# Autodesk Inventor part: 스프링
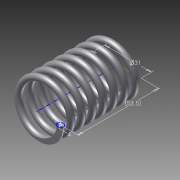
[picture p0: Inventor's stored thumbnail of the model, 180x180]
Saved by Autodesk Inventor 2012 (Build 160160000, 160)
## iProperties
Created: 2014-12
Part Number: 스프링
Material: Default
Document SubType Name: Modeling
Designer: Owner
Mass: 9.02095 g
Surface Area: 91.4446 cm^2
Volume: 9.02095 cm^3
Density: 1 g/cm^3
Author: Owner
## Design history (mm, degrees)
sketch "스케치1"
  geometry: L1 (0, 0)-(15.5, 0); L2 (15.5, 0)-(15.5, 48.5); L3 (15.5, 48.5)-(0, 48.5); L4 (0, 48.5)-(0, 0); C1 r 2 at (15.5, 0)
  constraints: 8 end point, 2 parallel, 1 centre point, 1 coincident, 1 horizontal, 1 perpendicular
  dimensions: "d0" = 4 diameter of C1; "d1" = 31 diameter of L2 L4; "d2" = 48.5 distance of L1.end L2.end (derived)
feature "코일1" pitch "d3" = 10; turns "d5" = 7.5; dims "d4" = 48.5 (= d2), "d6" = 0, angle "d7" = 90 deg, angle "d8" = 90 deg, "d9" = 0, "d10" = 0
sketch "스케치2"
  geometry: L1 (-17.5, 0)-(-13.5, 0) reference; 1 further point
  constraints: 1 horizontal alignment
extrude "돌출1" cut sketch "스케치2" stored distance "d11" = 10; taper "d12" = 0 deg
node "작업 평면1"
sketch "스케치3"
  geometry: L1 (13.5, 0)-(17.5, 0) reference; 1 further point
  constraints: 1 horizontal alignment
extrude "돌출2" cut sketch "스케치3" stored distance "d13" = 10; taper "d14" = 0 deg
node "솔리드1"
node "절단 모서리 투영1"
node "절단 모서리 투영2"
